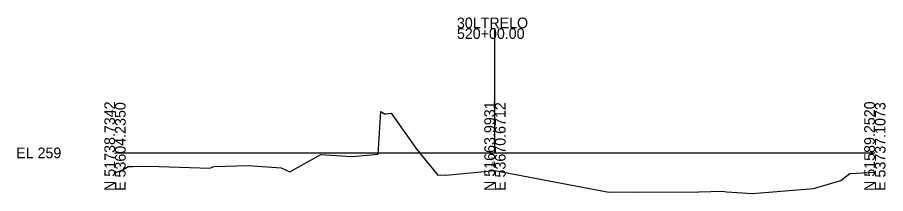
# Model space of a CAD drawing. Extents: x 3756 to 3985, y 89097 to 93134.
# Drawn here: x 3756 to 3984.5, y 91096.5 to 91142.7 of the extents above; entities that cross this region are included whole.
import ezdxf

# ---------------------------------------------------------------- set-up
doc = ezdxf.new("R2010")
doc.units = 0
for name, color, linetype in [('Level 10', 7, 'Continuous'), ('Level 60', 7, 'Continuous'), ('Level 63', 7, 'Continuous')]:
    doc.layers.add(name, color=color, linetype=linetype)

msp = doc.modelspace()

# ---------------------------------------------------------------- linework, layer by layer
at = {"layer": 'Level 60'}
for p, q in [((3850.92, 91106.86), (3851.64, 91118.07)), ((3851.64, 91118.07), (3852.59, 91117.45)), ((3852.59, 91117.45), (3853, 91117.45)), ((3853, 91117.45), (3854.38, 91117.61)), ((3854.38, 91117.61), (3861.11, 91108.07)), ((3861.11, 91108.07), (3866.68, 91101.33)), ((3827.74, 91102.16), (3835.85, 91106.78)), ((3835.85, 91106.78), (3844.13, 91106.25)), ((3844.13, 91106.25), (3850.92, 91106.86)), ((3783.72, 91102.7), (3785.14, 91103.57)), ((3785.14, 91103.57), (3786.41, 91103.59)), ((3786.41, 91103.59), (3790.62, 91103.66)), ((3790.62, 91103.66), (3806.65, 91103.18)), ((3806.65, 91103.18), (3807.69, 91103.62)), ((3807.69, 91103.62), (3816.76, 91103.88)), ((3816.76, 91103.88), (3825.45, 91103.28)), ((3825.45, 91103.28), (3827.74, 91102.16)), ((3781.68, 91101.9), (3783.72, 91102.7)), ((3866.68, 91101.33), (3867.45, 91101.38)), ((3867.45, 91101.38), (3868.75, 91101.35)), ((3868.75, 91101.35), (3881.68, 91102.52)), ((3881.68, 91102.52), (3911.68, 91096.83)), ((3972.7, 91099.9), (3975.07, 91101.76)), ((3975.07, 91101.76), (3981.68, 91102.14)), ((3965.52, 91097.84), (3972.7, 91099.9)), ((3911.68, 91096.83), (3916.24, 91096.97)), ((3916.24, 91096.97), (3919.03, 91096.84)), ((3919.03, 91096.84), (3935.38, 91096.92)), ((3935.38, 91096.92), (3941.68, 91097.1)), ((3941.68, 91097.1), (3942.62, 91096.9)), ((3942.62, 91096.9), (3949.48, 91096.47)), ((3949.48, 91096.47), (3965.52, 91097.84))]:
    msp.add_line(p, q, dxfattribs=at)
at = {"layer": 'Level 63'}
for p, q in [((3881.68, 91107.16), (3881.68, 91139.9)), ((3781.68, 91107.16), (3881.68, 91107.16)), ((3881.68, 91107.16), (3981.68, 91107.16))]:
    msp.add_line(p, q, dxfattribs=at)

# ---------------------------------------------------------------- texts
at = {"layer": 'Level 10'}
msp.add_text('254.36', height=0.6, rotation=90, dxfattribs=at).set_placement((3881.28, 91103.52))
at = {"layer": 'Level 63'}
for s, p in [('30LTRELO', (3871.68, 91139.9)), ('520+00.00', (3871.68, 91137.1)), ('EL 259', (3755.68, 91105.76))]:
    msp.add_text(s, height=2.8, dxfattribs=at).set_placement(p)
for s, p in [('N 51738.7342', (3781.68, 91097.16)), ('E 53604.2350', (3784.48, 91097.16)), ('N 51663.9931', (3881.68, 91097.16)), ('E 53670.6712', (3884.48, 91097.16)), ('N 51589.2520', (3981.68, 91097.16)), ('E 53737.1073', (3984.48, 91097.16))]:
    msp.add_text(s, height=2.8, rotation=90, dxfattribs=at).set_placement(p)

doc.saveas('drawing.dxf')
